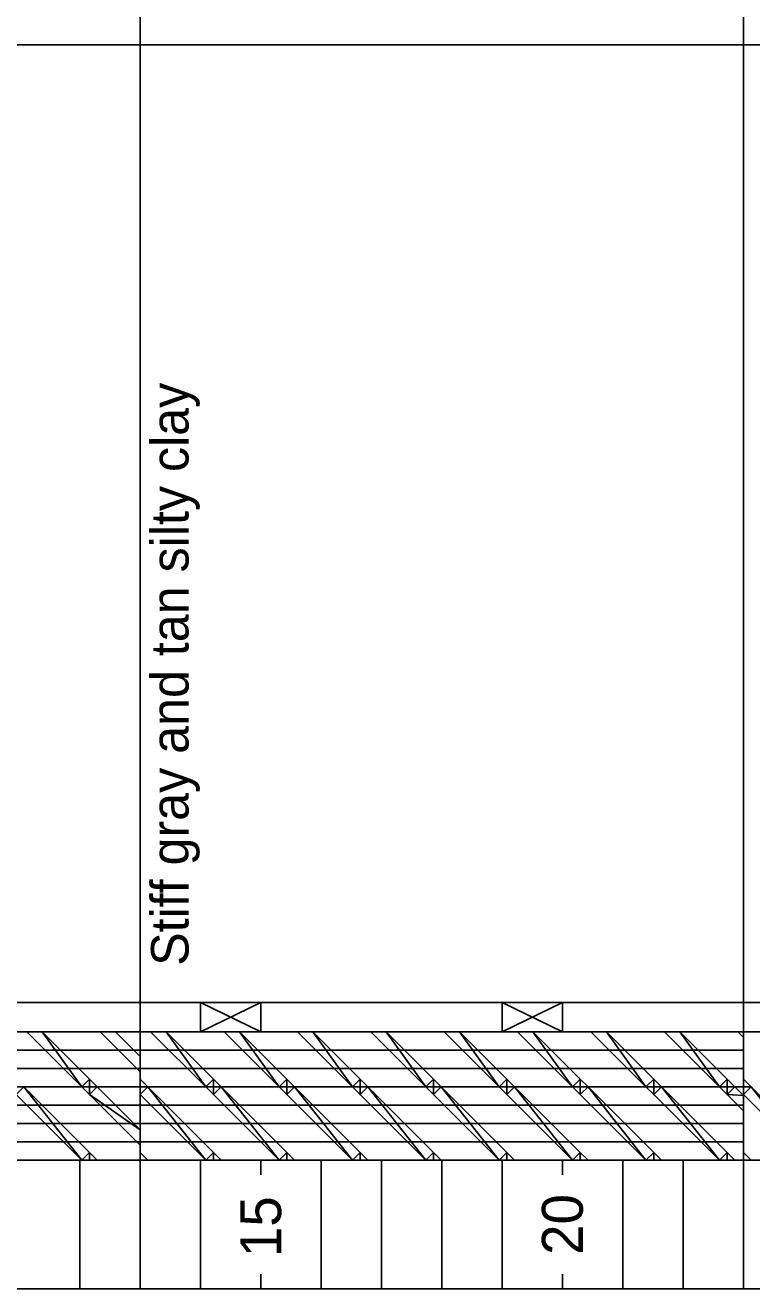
# Model space of a CAD drawing. Extents: x 1313964 to 1316843, y 2087046 to 2096619.
# Drawn here: x 1314000.47 to 1314012.51, y 2089818.7 to 2089839.64 of the extents above; entities that cross this region are included whole.
import ezdxf

# ---------------------------------------------------------------- set-up
doc = ezdxf.new("R2010")
doc.units = 0
doc.layers.add('B-Sub-Contour', color=7, linetype='Continuous')

msp = doc.modelspace()

# ---------------------------------------------------------------- linework, layer by layer
at = {"layer": 'B-Sub-Contour'}
for points in [[(1314036.804, 2089818.705), (1314036.804, 2089861.576), (1313975.385, 2089861.576), (1313975.385, 2089818.705), (1314036.804, 2089818.705)], [(1314002.372, 2089839.319), (1314002.372, 2089859.752)], [(1314012.372, 2089839.319), (1314012.372, 2089859.752)], [(1314034.372, 2089839.319), (1313982.683, 2089839.319)], [(1314002.372, 2089823.448), (1314002.372, 2089839.319)], [(1314012.372, 2089823.448), (1314012.372, 2089839.319)], [(1314034.372, 2089823.448), (1313989.372, 2089823.448)], [(1314002.372, 2089822.961), (1314002.372, 2089823.448)], [(1314003.372, 2089822.961), (1314004.372, 2089823.448)], [(1314004.372, 2089822.961), (1314003.372, 2089823.448)], [(1314003.372, 2089822.961), (1314003.372, 2089823.448)], [(1314004.372, 2089822.961), (1314004.372, 2089823.448)], [(1314008.372, 2089822.961), (1314009.372, 2089823.448)], [(1314009.372, 2089822.961), (1314008.372, 2089823.448)], [(1314008.372, 2089822.961), (1314008.372, 2089823.448)], [(1314009.372, 2089822.961), (1314009.372, 2089823.448)], [(1314012.372, 2089822.961), (1314012.372, 2089823.448)], [(1314034.372, 2089822.961), (1313982.683, 2089822.961)], [(1314002.372, 2089820.833), (1314002.372, 2089822.961)], [(1314012.372, 2089820.833), (1314012.372, 2089822.961)], [(1314002.372, 2089822.657), (1313989.372, 2089822.657)], [(1314012.372, 2089822.657), (1314002.372, 2089822.657)], [(1314002.372, 2089822.353), (1313989.372, 2089822.353)], [(1314012.372, 2089822.353), (1314002.372, 2089822.353)], [(1314002.372, 2089822.049), (1313989.372, 2089822.049)], [(1314012.372, 2089822.049), (1314002.372, 2089822.049)], [(1314002.372, 2089821.745), (1313989.372, 2089821.745)], [(1314012.372, 2089821.745), (1314002.372, 2089821.745)], [(1314002.372, 2089821.441), (1313989.372, 2089821.441)], [(1314012.372, 2089821.441), (1314002.372, 2089821.441)], [(1314002.372, 2089821.137), (1313989.372, 2089821.137)], [(1314012.372, 2089821.137), (1314002.372, 2089821.137)], [(1314034.372, 2089820.833), (1313982.683, 2089820.833)], [(1314001.372, 2089818.705), (1314001.372, 2089820.833)], [(1314001.372, 2089818.705), (1314001.372, 2089820.833)], [(1314002.372, 2089818.705), (1314002.372, 2089820.833)], [(1314003.372, 2089818.705), (1314003.372, 2089820.833)], [(1314003.372, 2089818.705), (1314003.372, 2089820.833)], [(1314004.372, 2089820.59), (1314004.372, 2089820.833)], [(1314005.372, 2089818.705), (1314005.372, 2089820.833)], [(1314005.372, 2089818.705), (1314005.372, 2089820.833)], [(1314006.372, 2089818.705), (1314006.372, 2089820.833)], [(1314007.372, 2089818.705), (1314007.372, 2089820.833)], [(1314007.372, 2089818.705), (1314007.372, 2089820.833)], [(1314008.372, 2089818.705), (1314008.372, 2089820.833)], [(1314009.372, 2089820.59), (1314009.372, 2089820.833)], [(1314009.372, 2089820.59), (1314009.372, 2089820.833)], [(1314010.372, 2089818.705), (1314010.372, 2089820.833)], [(1314011.372, 2089818.705), (1314011.372, 2089820.833)], [(1314011.372, 2089818.705), (1314011.372, 2089820.833)], [(1314012.372, 2089818.705), (1314012.372, 2089820.833)], [(1314004.372, 2089818.705), (1314004.372, 2089818.948)], [(1314009.372, 2089818.705), (1314009.372, 2089818.948)], [(1314009.372, 2089818.705), (1314009.372, 2089818.948)]]:
    msp.add_lwpolyline(points, dxfattribs=at)
for points in [[(1314001.406, 2089822.049), (1314000.749, 2089822.961), (1314000.494, 2089822.961), (1314001.406, 2089822.049)], [(1314001.406, 2089822.049), (1314001.534, 2089822.177), (1314000.749, 2089822.961), (1314001.406, 2089822.049)], [(1314001.966, 2089822.961), (1314001.71, 2089822.961), (1314002.372, 2089822.3), (1314002.372, 2089822.555)], [(1314003.46, 2089822.049), (1314002.803, 2089822.961), (1314002.548, 2089822.961), (1314003.46, 2089822.049)], [(1314003.46, 2089822.049), (1314003.588, 2089822.177), (1314002.803, 2089822.961), (1314003.46, 2089822.049)], [(1314004.676, 2089822.049), (1314004.02, 2089822.961), (1314003.764, 2089822.961), (1314004.676, 2089822.049)], [(1314004.676, 2089822.049), (1314004.804, 2089822.177), (1314004.02, 2089822.961), (1314004.676, 2089822.049)], [(1314005.893, 2089822.049), (1314005.236, 2089822.961), (1314004.98, 2089822.961), (1314005.893, 2089822.049)], [(1314005.893, 2089822.049), (1314006.02, 2089822.177), (1314005.236, 2089822.961), (1314005.893, 2089822.049)], [(1314007.109, 2089822.049), (1314006.452, 2089822.961), (1314006.197, 2089822.961), (1314007.109, 2089822.049)], [(1314007.109, 2089822.049), (1314007.237, 2089822.177), (1314006.452, 2089822.961), (1314007.109, 2089822.049)], [(1314008.325, 2089822.049), (1314007.668, 2089822.961), (1314007.413, 2089822.961), (1314008.325, 2089822.049)], [(1314008.325, 2089822.049), (1314008.453, 2089822.177), (1314007.668, 2089822.961), (1314008.325, 2089822.049)], [(1314009.541, 2089822.049), (1314008.884, 2089822.961), (1314008.629, 2089822.961), (1314009.541, 2089822.049)], [(1314009.541, 2089822.049), (1314009.669, 2089822.177), (1314008.884, 2089822.961), (1314009.541, 2089822.049)], [(1314010.757, 2089822.049), (1314010.101, 2089822.961), (1314009.845, 2089822.961), (1314010.757, 2089822.049)], [(1314010.757, 2089822.049), (1314010.885, 2089822.177), (1314010.101, 2089822.961), (1314010.757, 2089822.049)], [(1314011.974, 2089822.049), (1314011.317, 2089822.961), (1314011.062, 2089822.961), (1314011.974, 2089822.049)], [(1314011.974, 2089822.049), (1314012.101, 2089822.177), (1314011.317, 2089822.961), (1314011.974, 2089822.049)], [(1314012.372, 2089822.867), (1314012.372, 2089822.961), (1314012.278, 2089822.961), (1314012.372, 2089822.867)], [(1314001.406, 2089820.833), (1314000.445, 2089822.049), (1314000.318, 2089821.922), (1314001.406, 2089820.833)], [(1314001.406, 2089820.833), (1314001.534, 2089820.961), (1314000.445, 2089822.049), (1314001.406, 2089820.833)], [(1314001.406, 2089822.049), (1314001.534, 2089822.049), (1314001.534, 2089822.177), (1314001.406, 2089822.049)], [(1314001.534, 2089822.049), (1314001.534, 2089821.922), (1314001.406, 2089822.049), (1314001.534, 2089822.049)], [(1314001.662, 2089822.049), (1314001.534, 2089822.049), (1314001.534, 2089822.177), (1314001.662, 2089822.049)], [(1314001.662, 2089822.049), (1314001.534, 2089822.049), (1314001.534, 2089821.922), (1314001.662, 2089822.049)], [(1314001.534, 2089821.922), (1314002.372, 2089821.339), (1314001.662, 2089822.049), (1314001.534, 2089821.922)], [(1314002.499, 2089822.049), (1314002.372, 2089822.049), (1314002.372, 2089822.177), (1314002.499, 2089822.049)], [(1314002.499, 2089822.049), (1314002.372, 2089822.049), (1314002.372, 2089821.922), (1314002.499, 2089822.049)], [(1314003.46, 2089820.833), (1314002.499, 2089822.049), (1314002.372, 2089821.922), (1314003.46, 2089820.833)], [(1314003.46, 2089820.833), (1314003.588, 2089820.961), (1314002.499, 2089822.049), (1314003.46, 2089820.833)], [(1314003.46, 2089822.049), (1314003.588, 2089822.049), (1314003.588, 2089822.177), (1314003.46, 2089822.049)], [(1314003.588, 2089822.049), (1314003.588, 2089821.922), (1314003.46, 2089822.049), (1314003.588, 2089822.049)], [(1314003.716, 2089822.049), (1314003.588, 2089822.049), (1314003.588, 2089822.177), (1314003.716, 2089822.049)], [(1314003.716, 2089822.049), (1314003.588, 2089822.049), (1314003.588, 2089821.922), (1314003.716, 2089822.049)], [(1314004.676, 2089820.833), (1314003.716, 2089822.049), (1314003.588, 2089821.922), (1314004.676, 2089820.833)], [(1314004.676, 2089820.833), (1314004.804, 2089820.961), (1314003.716, 2089822.049), (1314004.676, 2089820.833)], [(1314004.676, 2089822.049), (1314004.804, 2089822.049), (1314004.804, 2089822.177), (1314004.676, 2089822.049)], [(1314004.804, 2089822.049), (1314004.804, 2089821.922), (1314004.676, 2089822.049), (1314004.804, 2089822.049)], [(1314004.932, 2089822.049), (1314004.804, 2089822.049), (1314004.804, 2089822.177), (1314004.932, 2089822.049)], [(1314004.932, 2089822.049), (1314004.804, 2089822.049), (1314004.804, 2089821.922), (1314004.932, 2089822.049)], [(1314005.893, 2089820.833), (1314004.932, 2089822.049), (1314004.804, 2089821.922), (1314005.893, 2089820.833)], [(1314005.893, 2089820.833), (1314006.02, 2089820.961), (1314004.932, 2089822.049), (1314005.893, 2089820.833)], [(1314005.893, 2089822.049), (1314006.02, 2089822.049), (1314006.02, 2089822.177), (1314005.893, 2089822.049)], [(1314006.02, 2089822.049), (1314006.02, 2089821.922), (1314005.893, 2089822.049), (1314006.02, 2089822.049)], [(1314006.148, 2089822.049), (1314006.02, 2089822.049), (1314006.02, 2089822.177), (1314006.148, 2089822.049)], [(1314006.148, 2089822.049), (1314006.02, 2089822.049), (1314006.02, 2089821.922), (1314006.148, 2089822.049)], [(1314007.109, 2089820.833), (1314006.148, 2089822.049), (1314006.02, 2089821.922), (1314007.109, 2089820.833)], [(1314007.109, 2089820.833), (1314007.237, 2089820.961), (1314006.148, 2089822.049), (1314007.109, 2089820.833)], [(1314007.109, 2089822.049), (1314007.237, 2089822.049), (1314007.237, 2089822.177), (1314007.109, 2089822.049)], [(1314007.237, 2089822.049), (1314007.237, 2089821.922), (1314007.109, 2089822.049), (1314007.237, 2089822.049)], [(1314007.364, 2089822.049), (1314007.237, 2089822.049), (1314007.237, 2089822.177), (1314007.364, 2089822.049)], [(1314007.364, 2089822.049), (1314007.237, 2089822.049), (1314007.237, 2089821.922), (1314007.364, 2089822.049)], [(1314008.325, 2089820.833), (1314007.364, 2089822.049), (1314007.237, 2089821.922), (1314008.325, 2089820.833)], [(1314008.325, 2089820.833), (1314008.453, 2089820.961), (1314007.364, 2089822.049), (1314008.325, 2089820.833)], [(1314008.325, 2089822.049), (1314008.453, 2089822.049), (1314008.453, 2089822.177), (1314008.325, 2089822.049)], [(1314008.453, 2089822.049), (1314008.453, 2089821.922), (1314008.325, 2089822.049), (1314008.453, 2089822.049)], [(1314008.58, 2089822.049), (1314008.453, 2089822.049), (1314008.453, 2089822.177), (1314008.58, 2089822.049)], [(1314008.58, 2089822.049), (1314008.453, 2089822.049), (1314008.453, 2089821.922), (1314008.58, 2089822.049)], [(1314009.541, 2089820.833), (1314008.58, 2089822.049), (1314008.453, 2089821.922), (1314009.541, 2089820.833)], [(1314009.541, 2089820.833), (1314009.669, 2089820.961), (1314008.58, 2089822.049), (1314009.541, 2089820.833)], [(1314009.541, 2089822.049), (1314009.669, 2089822.049), (1314009.669, 2089822.177), (1314009.541, 2089822.049)], [(1314009.669, 2089822.049), (1314009.669, 2089821.922), (1314009.541, 2089822.049), (1314009.669, 2089822.049)], [(1314009.797, 2089822.049), (1314009.669, 2089822.049), (1314009.669, 2089822.177), (1314009.797, 2089822.049)], [(1314009.797, 2089822.049), (1314009.669, 2089822.049), (1314009.669, 2089821.922), (1314009.797, 2089822.049)], [(1314010.757, 2089820.833), (1314009.797, 2089822.049), (1314009.669, 2089821.922), (1314010.757, 2089820.833)], [(1314010.757, 2089820.833), (1314010.885, 2089820.961), (1314009.797, 2089822.049), (1314010.757, 2089820.833)], [(1314010.757, 2089822.049), (1314010.885, 2089822.049), (1314010.885, 2089822.177), (1314010.757, 2089822.049)], [(1314010.885, 2089822.049), (1314010.885, 2089821.922), (1314010.757, 2089822.049), (1314010.885, 2089822.049)], [(1314011.013, 2089822.049), (1314010.885, 2089822.049), (1314010.885, 2089822.177), (1314011.013, 2089822.049)], [(1314011.013, 2089822.049), (1314010.885, 2089822.049), (1314010.885, 2089821.922), (1314011.013, 2089822.049)], [(1314011.974, 2089820.833), (1314011.013, 2089822.049), (1314010.885, 2089821.922), (1314011.974, 2089820.833)], [(1314011.974, 2089820.833), (1314012.101, 2089820.961), (1314011.013, 2089822.049), (1314011.974, 2089820.833)], [(1314011.974, 2089822.049), (1314012.101, 2089822.049), (1314012.101, 2089822.177), (1314011.974, 2089822.049)], [(1314012.101, 2089822.049), (1314012.101, 2089821.922), (1314011.974, 2089822.049), (1314012.101, 2089822.049)], [(1314012.229, 2089822.049), (1314012.101, 2089822.049), (1314012.101, 2089822.177), (1314012.229, 2089822.049)], [(1314012.229, 2089822.049), (1314012.101, 2089822.049), (1314012.101, 2089821.922), (1314012.229, 2089822.049)], [(1314012.101, 2089821.922), (1314012.372, 2089821.907), (1314012.229, 2089822.049), (1314012.101, 2089821.922)], [(1314012.499, 2089822.049), (1314012.372, 2089822.049), (1314012.372, 2089822.177), (1314012.499, 2089822.049)], [(1314012.499, 2089822.049), (1314012.372, 2089822.049), (1314012.372, 2089821.922), (1314012.499, 2089822.049)], [(1314013.46, 2089820.833), (1314012.499, 2089822.049), (1314012.372, 2089821.922), (1314013.46, 2089820.833)], [(1314013.46, 2089820.833), (1314013.588, 2089820.961), (1314012.499, 2089822.049), (1314013.46, 2089820.833)], [(1314001.534, 2089821.922), (1314002.372, 2089821.084), (1314002.372, 2089821.339), (1314001.534, 2089821.922)], [(1314012.101, 2089821.922), (1314012.372, 2089821.651), (1314012.372, 2089821.907), (1314012.101, 2089821.922)], [(1314001.406, 2089820.833), (1314001.534, 2089820.833), (1314001.534, 2089820.961), (1314001.406, 2089820.833)], [(1314001.662, 2089820.833), (1314001.534, 2089820.833), (1314001.534, 2089820.961), (1314001.662, 2089820.833)], [(1314002.499, 2089820.833), (1314002.372, 2089820.833), (1314002.372, 2089820.961), (1314002.499, 2089820.833)], [(1314003.46, 2089820.833), (1314003.588, 2089820.833), (1314003.588, 2089820.961), (1314003.46, 2089820.833)], [(1314003.716, 2089820.833), (1314003.588, 2089820.833), (1314003.588, 2089820.961), (1314003.716, 2089820.833)], [(1314004.676, 2089820.833), (1314004.804, 2089820.833), (1314004.804, 2089820.961), (1314004.676, 2089820.833)], [(1314004.932, 2089820.833), (1314004.804, 2089820.833), (1314004.804, 2089820.961), (1314004.932, 2089820.833)], [(1314005.893, 2089820.833), (1314006.02, 2089820.833), (1314006.02, 2089820.961), (1314005.893, 2089820.833)], [(1314006.148, 2089820.833), (1314006.02, 2089820.833), (1314006.02, 2089820.961), (1314006.148, 2089820.833)], [(1314007.109, 2089820.833), (1314007.237, 2089820.833), (1314007.237, 2089820.961), (1314007.109, 2089820.833)], [(1314007.364, 2089820.833), (1314007.237, 2089820.833), (1314007.237, 2089820.961), (1314007.364, 2089820.833)], [(1314008.325, 2089820.833), (1314008.453, 2089820.833), (1314008.453, 2089820.961), (1314008.325, 2089820.833)], [(1314008.58, 2089820.833), (1314008.453, 2089820.833), (1314008.453, 2089820.961), (1314008.58, 2089820.833)], [(1314009.541, 2089820.833), (1314009.669, 2089820.833), (1314009.669, 2089820.961), (1314009.541, 2089820.833)], [(1314009.797, 2089820.833), (1314009.669, 2089820.833), (1314009.669, 2089820.961), (1314009.797, 2089820.833)], [(1314010.757, 2089820.833), (1314010.885, 2089820.833), (1314010.885, 2089820.961), (1314010.757, 2089820.833)], [(1314011.013, 2089820.833), (1314010.885, 2089820.833), (1314010.885, 2089820.961), (1314011.013, 2089820.833)], [(1314011.974, 2089820.833), (1314012.101, 2089820.833), (1314012.101, 2089820.961), (1314011.974, 2089820.833)], [(1314012.229, 2089820.833), (1314012.101, 2089820.833), (1314012.101, 2089820.961), (1314012.229, 2089820.833)], [(1314012.499, 2089820.833), (1314012.372, 2089820.833), (1314012.372, 2089820.961), (1314012.499, 2089820.833)]]:
    msp.add_lwpolyline(points, close=True, dxfattribs=at)

# ---------------------------------------------------------------- texts
for s, height, p in [('Stiff gray and tan silty clay', 0.62209, (1314003.176, 2089824.056)), ('15', 0.6786, (1314004.711, 2089819.227)), ('20', 0.6786, (1314009.711, 2089819.265)), ('20', 0.6786, (1314009.711, 2089819.265))]:
    msp.add_text(s, height=height, rotation=90, dxfattribs=at).set_placement(p)

doc.saveas('drawing.dxf')
